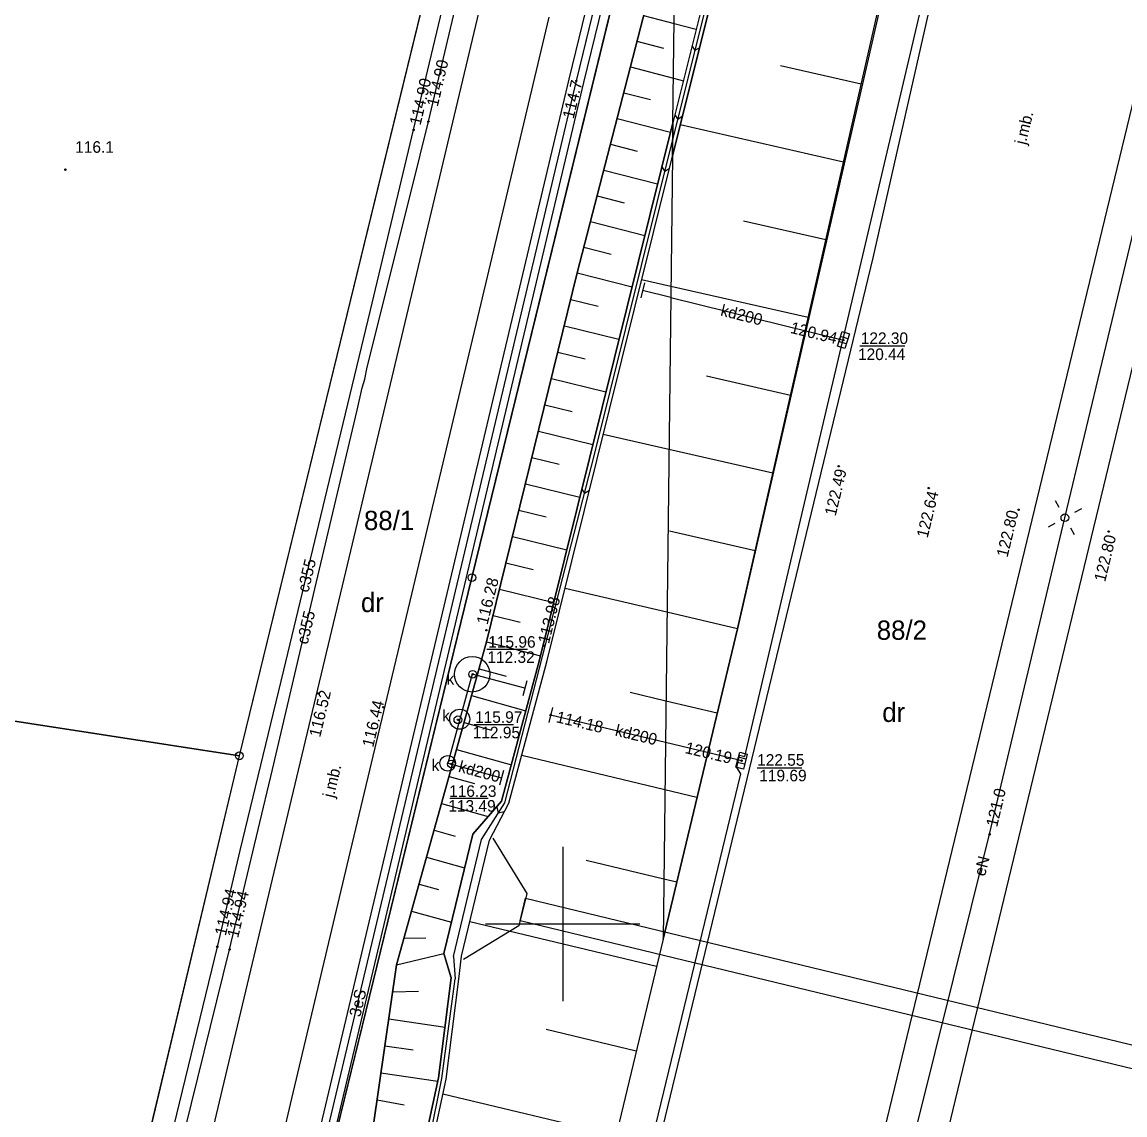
# Model space of a CAD drawing. Extents: x 6424617 to 6425697, y 5665845 to 5667190.
# Drawn here: x 6425265 to 6425336.4, y 5666387.6 to 5666458.4 of the extents above; entities that cross this region are included whole.
import ezdxf

# ---------------------------------------------------------------- set-up
doc = ezdxf.new("R2010")
doc.units = 0
for name, color, linetype in [('Warstwa 1', 7, 'Continuous'), ('Warstwa 10', 7, 'Continuous'), ('Warstwa 11', 7, 'Continuous'), ('Warstwa 12', 7, 'Continuous'), ('Warstwa 13', 7, 'Continuous'), ('Warstwa 14', 7, 'Continuous'), ('Warstwa 15', 7, 'Continuous'), ('Warstwa 16', 7, 'Continuous'), ('Warstwa 2', 7, 'Continuous'), ('Warstwa 20', 7, 'Continuous'), ('Warstwa 21', 7, 'Continuous'), ('Warstwa 22', 7, 'Continuous'), ('Warstwa 25', 7, 'Continuous'), ('Warstwa 4', 7, 'Continuous'), ('Warstwa 47', 7, 'Continuous'), ('Warstwa 5', 7, 'Continuous'), ('Warstwa 6', 7, 'Continuous'), ('Warstwa 61', 7, 'Continuous'), ('Warstwa 63', 7, 'Continuous'), ('Warstwa 8', 7, 'Continuous'), ('Warstwa 9', 7, 'Continuous')]:
    doc.layers.add(name, color=color, linetype=linetype)

msp = doc.modelspace()

# ---------------------------------------------------------------- linework, layer by layer
at = {"layer": 'Warstwa 1'}
for p, q in [((6425294.11, 5666422.45), (6425333.09, 5666581.65)), ((6425294.11, 5666422.45), (6425333.09, 5666581.65)), ((6425279.037, 5666410.906), (6425312.219, 5666546.795)), ((6425279.037, 5666410.906), (6425312.219, 5666546.795)), ((6425272.8, 5666335.34), (6425294.11, 5666422.45)), ((6425272.8, 5666335.34), (6425294.11, 5666422.45)), ((6425251.855, 5666415.084), (6425279.037, 5666410.906)), ((6425251.855, 5666415.084), (6425279.037, 5666410.906)), ((6425244.275, 5666264.977), (6425279.037, 5666410.906)), ((6425244.275, 5666264.977), (6425279.037, 5666410.906))]:
    msp.add_line(p, q, dxfattribs=at)
at = {"layer": 'Warstwa 10'}
for points in [[(6425267.728, 5666315.146), (6425271.19, 5666329.86), (6425276.57, 5666352.13), (6425283.28, 5666380.44), (6425290.28, 5666409.92), (6425300.88, 5666454.64), (6425307.494, 5666481.767)], [(6425295.47, 5666405.57), (6425297.66, 5666401.99), (6425297.15, 5666399.9), (6425293.57, 5666397.71)]]:
    msp.add_lwpolyline(points, dxfattribs=at)
for centre in [(6425294.11, 5666422.45), (6425279.037, 5666410.906)]:
    msp.add_circle(centre, 0.25, dxfattribs=at)
at = {"layer": 'Warstwa 12'}
for points in [[(6425274.8, 5666386.88), (6425277.61, 5666398.54), (6425279.1, 5666404.78), (6425281.92, 5666416.45), (6425284.73, 5666428.13), (6425287.53, 5666439.79), (6425290.33, 5666451.46), (6425293.1, 5666463.15), (6425295.91, 5666474.81), (6425298.69, 5666486.5), (6425301.54, 5666498.35), (6425304.4, 5666509.95), (6425307.24, 5666521.52), (6425307.5, 5666522.71), (6425307.25, 5666523.17), (6425306.05, 5666523.49), (6425298.26, 5666525.66), (6425296.82, 5666526.06), (6425295.28, 5666526.18), (6425283.35, 5666527.26), (6425271.38, 5666528.38), (6425259.45, 5666529.58)], [(6425305.48, 5666314.773), (6425311.14, 5666338.26), (6425315.72, 5666356.59), (6425314.85, 5666358.59), (6425315.59, 5666360.88), (6425316.68, 5666361.57), (6425321.81, 5666382.32), (6425327.66, 5666405.82), (6425332.54, 5666426.33), (6425338.92, 5666452.89), (6425344.68, 5666476.52), (6425348.06, 5666490.52), (6425353.32, 5666512.48), (6425356.9, 5666527.18)], [(6425275.52, 5666386.72), (6425278.4, 5666398.36), (6425281.19, 5666410.02), (6425283.93, 5666421.72), (6425286.67, 5666433.31), (6425286.99, 5666434.74), (6425287.17, 5666435.32), (6425287.32, 5666436.08), (6425290.21, 5666447.65), (6425291.29, 5666452), (6425294.06, 5666463.71), (6425296.87, 5666475.37), (6425299.68, 5666487.06), (6425302.52, 5666498.64), (6425305.3, 5666510.33), (6425307.971, 5666521.283)], [(6425306.998, 5666440.608), (6425305.17, 5666441.06)], [(6425306.998, 5666440.608), (6425317.94, 5666437.9), (6425318.19, 5666437.84)], [(6425297.54, 5666415.28), (6425294.13, 5666416.19), (6425293.32, 5666413.28), (6425292.54, 5666410.42), (6425296.02, 5666409.48)], [(6425306.65, 5666411.771), (6425299.21, 5666413.55)], [(6425311.59, 5666410.59), (6425311.34, 5666410.65), (6425306.65, 5666411.771)]]:
    msp.add_lwpolyline(points, dxfattribs=at)
at = {"layer": 'Warstwa 13'}
msp.add_circle((6425267.765, 5666448.883), 0.045, dxfattribs=at)
at = {"layer": 'Warstwa 14'}
for p, q in [((6425322.159, 5666437.447), (6425319.248, 5666437.447)), ((6425297.719, 5666417.786), (6425295.086, 5666417.786)), ((6425296.794, 5666412.918), (6425294.261, 5666412.918)), ((6425315.482, 5666410.1), (6425312.588, 5666410.1)), ((6425295.156, 5666408.136), (6425292.688, 5666408.136))]:
    msp.add_line(p, q, dxfattribs=at)
for centre in [(6425300.88, 5666454.64), (6425291.29, 5666452), (6425290.33, 5666451.46), (6425317.94, 5666437.9), (6425318.19, 5666437.84), (6425294.16, 5666416.19), (6425293.2, 5666413.24), (6425299.21, 5666413.55), (6425292.77, 5666410.38), (6425311.34, 5666410.65), (6425311.59, 5666410.59), (6425327.66, 5666405.82), (6425277.61, 5666398.54), (6425278.4, 5666398.36)]:
    msp.add_circle(centre, 0.045, dxfattribs=at)
at = {"layer": 'Warstwa 16'}
for centre, radius in [((6425294.13, 5666416.19), 1.15), ((6425293.32, 5666413.28), 0.65), ((6425292.54, 5666410.42), 0.5)]:
    msp.add_circle(centre, radius, dxfattribs=at)
at = {"layer": 'Warstwa 2'}
msp.add_circle((6425332.54, 5666426.33), 0.25, dxfattribs=at)
at = {"layer": 'Warstwa 20'}
for points in [[(6425306.496, 5666399.029), (6425311.317, 5666419.144), (6425338.808, 5666540.067), (6425344.652, 5666564.235)], [(6425292.98, 5666380.282), (6425290.492, 5666380.934), (6425289.337, 5666381.236), (6425286.21, 5666382.055), (6425287.707, 5666386.869), (6425289.227, 5666397.355), (6425295.057, 5666418.297), (6425300.94, 5666442.189), (6425307.315, 5666466.947)], [(6425306.496, 5666399.029), (6425300.821, 5666375.348), (6425289.41, 5666327.719), (6425285.185, 5666318.653), (6425284.331, 5666314.945)]]:
    msp.add_lwpolyline(points, dxfattribs=at)
at = {"layer": 'Warstwa 21'}
for p, q in [((6425305.29, 5666441.545), (6425305.05, 5666440.575)), ((6425297.67, 5666415.763), (6425297.41, 5666414.797)), ((6425299.327, 5666414.036), (6425299.093, 5666413.064)), ((6425296.15, 5666409.963), (6425295.89, 5666408.997))]:
    msp.add_line(p, q, dxfattribs=at)
for points in [[(6425307.108, 5666449.766), (6425311.778, 5666468.481), (6425334.917, 5666564.352)], [(6425334.457, 5666564.358), (6425324.684, 5666524.027), (6425311.3, 5666468.61), (6425307.134, 5666451.915)], [(6425292.98, 5666380.282), (6425290.684, 5666381.655), (6425289.535, 5666381.982), (6425291.018, 5666385.749), (6425291.946, 5666390.044), (6425292.773, 5666396.511), (6425292.291, 5666398.09), (6425294.162, 5666405.839), (6425296.03, 5666407.966), (6425298.497, 5666417.135), (6425304.161, 5666440), (6425307.134, 5666451.915)], [(6425270.982, 5666315.107), (6425272.032, 5666319.27), (6425277.811, 5666333.541), (6425285.262, 5666361.705), (6425288.33, 5666373.734), (6425289.376, 5666376.843), (6425292.365, 5666377.252), (6425292.98, 5666380.282), (6425290.684, 5666381.655), (6425291.516, 5666385.64), (6425292.444, 5666389.955), (6425293.272, 5666396.442), (6425293.428, 5666397.92), (6425295.255, 5666405.439), (6425296.508, 5666407.837), (6425298.975, 5666417.006), (6425304.639, 5666439.871), (6425307.108, 5666449.766)]]:
    msp.add_lwpolyline(points, dxfattribs=at)
at = {"layer": 'Warstwa 22'}
msp.add_lwpolyline([(6425352.7, 5666388.73), (6425359.81, 5666387.02), (6425359.721, 5666386.659), (6425384.611, 5666380.644), (6425384.259, 5666379.186), (6425359.369, 5666385.201), (6425359.28, 5666384.84), (6425352.17, 5666386.56), (6425352.257, 5666386.916), (6425297.227, 5666400.216), (6425297.583, 5666401.674), (6425352.613, 5666388.374), (6425352.7, 5666388.73)], dxfattribs=at)
at = {"layer": 'Warstwa 25'}
for centre in [(6425317.879, 5666429.669), (6425323.715, 5666428.253), (6425329.542, 5666426.847), (6425335.378, 5666425.431), (6425295.054, 5666419.04), (6425298.779, 5666418.04), (6425284.113, 5666414.953), (6425288.368, 5666414.056)]:
    msp.add_circle(centre, 0.045, dxfattribs=at)
at = {"layer": 'Warstwa 4'}
for p, q in [((6425318.373, 5666437.596), (6425317.898, 5666437.752)), ((6425318.482, 5666437.928), (6425318.007, 5666438.084)), ((6425311.789, 5666410.359), (6425311.305, 5666410.482)), ((6425311.875, 5666410.698), (6425311.391, 5666410.821))]:
    msp.add_line(p, q, dxfattribs=at)
for points in [[(6425318.583, 5666438.237), (6425318.272, 5666437.287), (6425317.797, 5666437.443), (6425318.108, 5666438.393)], [(6425311.956, 5666411.013), (6425311.709, 5666410.044), (6425311.224, 5666410.167), (6425311.471, 5666411.136)]]:
    msp.add_lwpolyline(points, close=True, dxfattribs=at)
for points in [[(6425332.174, 5666426.985), (6425331.93, 5666427.421)], [(6425333.195, 5666426.696), (6425333.631, 5666426.94)], [(6425331.885, 5666425.964), (6425331.449, 5666425.72)], [(6425332.906, 5666425.675), (6425333.15, 5666425.239)]]:
    msp.add_lwpolyline(points, dxfattribs=at)
for centre in [(6425294.16, 5666416.19), (6425293.2, 5666413.24), (6425292.77, 5666410.38)]:
    msp.add_circle(centre, 0.25, dxfattribs=at)
at = {"layer": 'Warstwa 47'}
for points in [[(6425344.651, 5666564.235), (6425344.106, 5666562.008), (6425311.317, 5666419.144), (6425306.496, 5666399.029)], [(6425306.496, 5666399.029), (6425300.821, 5666375.348), (6425289.41, 5666327.719), (6425285.185, 5666318.653), (6425284.331, 5666314.945)]]:
    msp.add_lwpolyline(points, dxfattribs=at)
at = {"layer": 'Warstwa 6'}
for points in [[(6425244.275, 5666264.977), (6425279.037, 5666410.906), (6425312.219, 5666546.795), (6425313.029, 5666550.146), (6425358.794, 5666739.45), (6425345.837, 5666783.728), (6425348.185, 5666793.45), (6425355.292, 5666837.846), (6425351.457, 5666842.463), (6425355.995, 5666841.398), (6425356.96, 5666840.82), (6425392.62, 5666819.33), (6425392.36, 5666816.84), (6425379.44, 5666763.67), (6425335.03, 5666581.17), (6425333.09, 5666581.65), (6425294.11, 5666422.45), (6425272.8, 5666335.34)], [(6425392.36, 5666816.84), (6425379.44, 5666763.67), (6425335.03, 5666581.17), (6425333.09, 5666581.65), (6425294.11, 5666422.45), (6425272.8, 5666335.34)], [(6425306.368, 5666388.415), (6425311.528, 5666409.747), (6425311.275, 5666410.152), (6425311.459, 5666410.938), (6425311.798, 5666410.862), (6425324.365, 5666464.253), (6425324.113, 5666464.668), (6425324.297, 5666465.454), (6425324.626, 5666465.379), (6425330.531, 5666491.58), (6425330.278, 5666491.995), (6425330.472, 5666492.782), (6425330.801, 5666492.706), (6425336.716, 5666518.898), (6425336.453, 5666519.323), (6425336.638, 5666520.11), (6425336.966, 5666520.034), (6425342.505, 5666544.261), (6425342.253, 5666544.676), (6425342.437, 5666545.463), (6425342.766, 5666545.387), (6425347.315, 5666564.203)], [(6425288.589, 5666314.894), (6425292.222, 5666329.989), (6425291.989, 5666330.384), (6425292.173, 5666331.171), (6425292.512, 5666331.084), (6425298.36, 5666355.247), (6425298.107, 5666355.651), (6425298.291, 5666356.438), (6425298.62, 5666356.362), (6425304.943, 5666382.487), (6425304.691, 5666382.892), (6425304.875, 5666383.678), (6425304.875, 5666383.678), (6425305.204, 5666383.602), (6425306.368, 5666388.415)]]:
    msp.add_lwpolyline(points, dxfattribs=at)
for points in [[(6425258.718, 5666441.763), (6425251.855, 5666415.084), (6425279.037, 5666410.906), (6425312.219, 5666546.795), (6425309.227, 5666547.531), (6425297.85, 5666522.097), (6425294.373, 5666514.928), (6425272.539, 5666497.33)], [(6425217.631, 5666278.959), (6425217.156, 5666267.745), (6425221.085, 5666266.797), (6425231.986, 5666266.785), (6425236.914, 5666266.626), (6425244.275, 5666264.977), (6425279.037, 5666410.906), (6425251.855, 5666415.084)]]:
    msp.add_lwpolyline(points, close=True, dxfattribs=at)
at = {"layer": 'Warstwa 61'}
msp.add_lwpolyline([(6425267.728, 5666315.146), (6425267.754, 5666315.255), (6425271.19, 5666329.86), (6425276.57, 5666352.13), (6425283.28, 5666380.44), (6425290.28, 5666409.92), (6425300.88, 5666454.64), (6425306.981, 5666479.664), (6425307.494, 5666481.768)], dxfattribs=at)
at = {"layer": 'Warstwa 63'}
for p, q in [((6425300, 5666405), (6425300, 5666395)), ((6425305, 5666400), (6425295, 5666400))]:
    msp.add_line(p, q, dxfattribs=at)
at = {"layer": 'Warstwa 8'}
for p, q in [((6425320.124, 5666443.173), (6425342.162, 5666540.747)), ((6425306.044, 5666325.418), (6425357.544, 5666538.388)), ((6425309.895, 5666324.328), (6425361.428, 5666537.448)), ((6425290.103, 5666440.344), (6425295.201, 5666461.749)), ((6425294.486, 5666439.304), (6425299.118, 5666458.757)), ((6425306.342, 5666386.207), (6425320.124, 5666443.173)), ((6425285.936, 5666422.833), (6425290.103, 5666440.344)), ((6425290.773, 5666423.736), (6425294.486, 5666439.304)), ((6425286.141, 5666404.273), (6425290.773, 5666423.736)), ((6425281.303, 5666403.37), (6425285.936, 5666422.833)), ((6425282.439, 5666388.705), (6425286.141, 5666404.273)), ((6425278.056, 5666389.755), (6425281.303, 5666403.37)), ((6425273.889, 5666372.234), (6425278.056, 5666389.755)), ((6425277.806, 5666369.252), (6425282.439, 5666388.705))]:
    msp.add_line(p, q, dxfattribs=at)
for points in [[(6425307.521, 5666483.989), (6425300.394, 5666454.757), (6425289.794, 5666410.035), (6425282.794, 5666380.555), (6425276.084, 5666352.246), (6425270.704, 5666329.976), (6425267.215, 5666315.152)], [(6425268.241, 5666315.14), (6425271.676, 5666329.744), (6425277.056, 5666352.014), (6425283.766, 5666380.325), (6425290.766, 5666409.805), (6425301.366, 5666454.523), (6425307.467, 5666479.546)]]:
    msp.add_lwpolyline(points, dxfattribs=at)
at = {"layer": 'Warstwa 9'}
for p, q in [((6425307.121, 5666450.84), (6425309.396, 5666459.917)), ((6425305.236, 5666458.873), (6425307.212, 5666458.364)), ((6425307.212, 5666458.364), (6425308.651, 5666457.994)), ((6425304.806, 5666457.204), (6425306.52, 5666456.763)), ((6425308.382, 5666456.915), (6425308.566, 5666456.607)), ((6425308.859, 5666456.782), (6425308.566, 5666456.607)), ((6425304.377, 5666455.536), (6425307.169, 5666454.817)), ((6425319.336, 5666454.414), (6425314.099, 5666455.604)), ((6425307.169, 5666454.817), (6425307.817, 5666454.65)), ((6425303.948, 5666453.868), (6425305.674, 5666453.423)), ((6425303.518, 5666452.199), (6425306.983, 5666451.307)), ((6425307.267, 5666452.447), (6425307.448, 5666452.144)), ((6425307.746, 5666452.323), (6425307.448, 5666452.144)), ((6425318.19, 5666449.375), (6425307.611, 5666451.78)), ((6425302.047, 5666430.422), (6425307.121, 5666450.841)), ((6425303.088, 5666450.53), (6425304.827, 5666450.083)), ((6425306.421, 5666449.057), (6425306.603, 5666448.755)), ((6425306.9, 5666448.934), (6425306.603, 5666448.755)), ((6425302.658, 5666448.862), (6425306.148, 5666447.964)), ((6425302.228, 5666447.194), (6425303.98, 5666446.743)), ((6425301.799, 5666445.526), (6425305.314, 5666444.621)), ((6425317.044, 5666444.336), (6425311.702, 5666445.551)), ((6425301.37, 5666443.858), (6425303.135, 5666443.408)), ((6425300.94, 5666442.189), (6425304.485, 5666441.297)), ((6425307.006, 5666441.319), (6425305.108, 5666441.751)), ((6425315.899, 5666439.298), (6425307.006, 5666441.319)), ((6425300.52, 5666440.482), (6425302.292, 5666440.042)), ((6425300.1, 5666438.776), (6425303.642, 5666437.905)), ((6425299.68, 5666437.07), (6425301.45, 5666436.634)), ((6425299.259, 5666435.363), (6425302.797, 5666434.493)), ((6425314.754, 5666434.26), (6425309.309, 5666435.497)), ((6425298.839, 5666433.657), (6425300.607, 5666433.222)), ((6425298.419, 5666431.95), (6425301.952, 5666431.081)), ((6425306.879, 5666430.751), (6425302.62, 5666431.719)), ((6425296.246, 5666407.87), (6425302.047, 5666430.422)), ((6425313.608, 5666429.221), (6425306.879, 5666430.751)), ((6425297.998, 5666430.243), (6425299.764, 5666429.809)), ((6425297.578, 5666428.536), (6425301.106, 5666427.668)), ((6425301.234, 5666428.183), (6425301.399, 5666427.903)), ((6425301.721, 5666428.093), (6425301.399, 5666427.903)), ((6425297.158, 5666426.83), (6425298.921, 5666426.396)), ((6425312.462, 5666424.182), (6425306.924, 5666425.458)), ((6425296.738, 5666425.123), (6425300.261, 5666424.256)), ((6425296.318, 5666423.416), (6425298.078, 5666422.983)), ((6425306.752, 5666420.208), (6425300.149, 5666421.747)), ((6425295.897, 5666421.71), (6425299.416, 5666420.844)), ((6425295.477, 5666420.004), (6425297.232, 5666419.557)), ((6425311.317, 5666419.144), (6425306.752, 5666420.208)), ((6425295.057, 5666418.297), (6425298.557, 5666417.378)), ((6425294.571, 5666416.552), (6425296.326, 5666416.077)), ((6425294.085, 5666414.807), (6425297.607, 5666413.827)), ((6425306.682, 5666414.455), (6425304.374, 5666415.001)), ((6425310.005, 5666413.67), (6425306.682, 5666414.455)), ((6425293.6, 5666413.062), (6425295.368, 5666412.569)), ((6425293.114, 5666411.316), (6425296.666, 5666410.328)), ((6425306.613, 5666408.694), (6425297.337, 5666410.917)), ((6425292.628, 5666409.571), (6425294.272, 5666409.114)), ((6425308.693, 5666408.195), (6425306.613, 5666408.694)), ((6425292.142, 5666407.826), (6425295.168, 5666406.984)), ((6425294.724, 5666405.492), (6425296.246, 5666407.87)), ((6425295.718, 5666407.611), (6425295.811, 5666407.191)), ((6425296.217, 5666407.28), (6425295.811, 5666407.191)), ((6425291.656, 5666406.081), (6425293.028, 5666405.699)), ((6425292.91, 5666397.908), (6425294.724, 5666405.492)), ((6425291.17, 5666404.336), (6425293.634, 5666403.651)), ((6425306.543, 5666402.921), (6425301.517, 5666404.126)), ((6425290.684, 5666402.59), (6425291.946, 5666402.24)), ((6425307.381, 5666402.72), (6425306.543, 5666402.921)), ((6425290.199, 5666400.845), (6425292.783, 5666400.126)), ((6425306.069, 5666397.246), (6425293.969, 5666400.147)), ((6425289.713, 5666399.1), (6425291.125, 5666399.104)), ((6425289.227, 5666397.355), (6425292.291, 5666398.09)), ((6425292.91, 5666397.908), (6425293.034, 5666396.456)), ((6425292.161, 5666389.994), (6425293.034, 5666396.456)), ((6425288.974, 5666395.608), (6425290.651, 5666395.659)), ((6425288.72, 5666393.86), (6425292.366, 5666393.332)), ((6425304.757, 5666391.772), (6425298.93, 5666393.169)), ((6425288.467, 5666392.112), (6425290.3, 5666391.846)), ((6425288.214, 5666390.364), (6425291.9, 5666389.83)), ((6425291.186, 5666385.187), (6425292.161, 5666389.994)), ((6425303.445, 5666386.297), (6425292.235, 5666388.984)), ((6425287.96, 5666388.616), (6425289.729, 5666388.291))]:
    msp.add_line(p, q, dxfattribs=at)
for points in [[(6425306.496, 5666399.029), (6425311.317, 5666419.144), (6425338.808, 5666540.067), (6425344.652, 5666564.235), (6425334.917, 5666564.352), (6425311.778, 5666468.481), (6425307.108, 5666449.766)], [(6425307.108, 5666449.766), (6425311.778, 5666468.481), (6425334.917, 5666564.352), (6425334.457, 5666564.358), (6425324.684, 5666524.027), (6425311.3, 5666468.61), (6425307.134, 5666451.915)], [(6425334.457, 5666564.358), (6425324.684, 5666524.027), (6425311.3, 5666468.61), (6425307.134, 5666451.915), (6425307.315, 5666466.947), (6425307.814, 5666468.883), (6425314.453, 5666496.422), (6425321.245, 5666524.099), (6425327.788, 5666549.679), (6425331.487, 5666564.394)], [(6425286.21, 5666382.055), (6425289.337, 5666381.236), (6425290.492, 5666380.934), (6425292.98, 5666380.282), (6425290.684, 5666381.655), (6425289.535, 5666381.982), (6425291.018, 5666385.749), (6425291.946, 5666390.044), (6425292.773, 5666396.511), (6425292.291, 5666398.09), (6425294.162, 5666405.839), (6425296.03, 5666407.966), (6425298.497, 5666417.135), (6425304.161, 5666440), (6425307.134, 5666451.915), (6425307.315, 5666466.947), (6425300.94, 5666442.189), (6425295.057, 5666418.297), (6425289.227, 5666397.355), (6425287.707, 5666386.869)], [(6425307.134, 5666451.915), (6425304.161, 5666440), (6425298.497, 5666417.135), (6425296.03, 5666407.966), (6425294.162, 5666405.839), (6425292.291, 5666398.09), (6425292.773, 5666396.511), (6425291.946, 5666390.044), (6425291.018, 5666385.749), (6425289.535, 5666381.982), (6425290.684, 5666381.655), (6425291.516, 5666385.64), (6425292.444, 5666389.955), (6425293.272, 5666396.442), (6425293.428, 5666397.92), (6425295.255, 5666405.439), (6425296.508, 5666407.837), (6425298.975, 5666417.006), (6425304.639, 5666439.871), (6425307.108, 5666449.766)], [(6425306.496, 5666399.029), (6425300.821, 5666375.348), (6425289.41, 5666327.719), (6425285.185, 5666318.653), (6425284.331, 5666314.945), (6425270.982, 5666315.107), (6425272.032, 5666319.27), (6425277.811, 5666333.541), (6425285.262, 5666361.705), (6425288.33, 5666373.734), (6425289.376, 5666376.843), (6425292.365, 5666377.252), (6425292.98, 5666380.282), (6425290.684, 5666381.655), (6425291.516, 5666385.64), (6425292.444, 5666389.955), (6425293.272, 5666396.442), (6425293.428, 5666397.92), (6425295.255, 5666405.439), (6425296.508, 5666407.837), (6425298.975, 5666417.006), (6425304.639, 5666439.871), (6425307.108, 5666449.766)]]:
    msp.add_lwpolyline(points, close=True, dxfattribs=at)

# ---------------------------------------------------------------- texts
at = {"layer": 'Warstwa 11'}
msp.add_text('3eS', height=0.75, rotation=76.64456, dxfattribs=at).set_placement((6425286.871, 5666393.942))
at = {"layer": 'Warstwa 13'}
msp.add_text('116.1', height=0.75, dxfattribs=at).set_placement((6425268.395, 5666449.977))
for s, rotation, p in [('kd200', 346.10089, (6425310.175, 5666439.436)), ('c355', 76.47268, (6425283.509, 5666421.45)), ('c355', 76.82218, (6425283.464, 5666418.085)), ('kd200', 346.55352, (6425303.346, 5666412.22)), ('kd200', 344.88622, (6425293.188, 5666409.883)), ('eN', 76.02004, (6425327.358, 5666403.055))]:
    msp.add_text(s, height=0.75, rotation=rotation, dxfattribs=at).set_placement(p)
at = {"layer": 'Warstwa 14'}
for s, rotation, p in [('114.90', 76.6904, (6425291.893, 5666452.921)), ('114.90', 76.66748, (6425290.777, 5666451.719)), ('114.7', 76.66748, (6425300.7, 5666452.139)), ('120.94', 346.10089, (6425314.697, 5666438.316)), ('114.18', 346.55352, (6425299.522, 5666413.089)), ('120.19', 346.55925, (6425307.877, 5666411.092)), ('121.0', 76.61592, (6425328.147, 5666406.253)), ('114.94', 76.57008, (6425278.155, 5666399.208)), ('114.94', 76.54143, (6425278.955, 5666399.066))]:
    msp.add_text(s, height=0.75, rotation=rotation, dxfattribs=at).set_placement(p)
for s, p in [('120.44', (6425319.132, 5666436.548)), ('112.32', (6425295.111, 5666416.926)), ('112.95', (6425294.161, 5666412.042)), ('119.69', (6425312.734, 5666409.253)), ('113.49', (6425292.581, 5666407.287))]:
    msp.add_text(s, height=0.75, dxfattribs=at).set_placement(p)
at = {"layer": 'Warstwa 15'}
for s, height, p in [('122.30', 0.75, (6425319.31, 5666437.589)), ('88/1', 1.25, (6425287.114, 5666425.532)), ('88/2', 1.25, (6425320.348, 5666418.423)), ('115.96', 0.75, (6425295.169, 5666417.911)), ('115.97', 0.75, (6425294.311, 5666413.042)), ('122.55', 0.75, (6425312.593, 5666410.263)), ('116.23', 0.75, (6425292.632, 5666408.243))]:
    msp.add_text(s, height=height, dxfattribs=at).set_placement(p)
at = {"layer": 'Warstwa 2'}
for p in [(6425286.916, 5666420.218), (6425320.703, 5666413.1)]:
    msp.add_text('dr', height=1.25, dxfattribs=at).set_placement(p)
at = {"layer": 'Warstwa 25'}
for s, rotation, p in [('122.49', 76.39819, (6425317.684, 5666426.406)), ('122.64', 76.39819, (6425323.644, 5666424.977)), ('122.80', 76.39819, (6425328.822, 5666423.729)), ('122.80', 76.40392, (6425335.15, 5666422.136)), ('116.28', 76.16901, (6425295.123, 5666419.361)), ('113.98', 76.0888, (6425299.103, 5666418.129)), ('116.52', 76.61019, (6425284.274, 5666412.067)), ('116.44', 76.61592, (6425287.711, 5666411.417))]:
    msp.add_text(s, height=0.75, rotation=rotation, dxfattribs=at).set_placement(p)
at = {"layer": 'Warstwa 5'}
for p in [(6425292.466, 5666415.514), (6425292.181, 5666413.132), (6425291.497, 5666409.922)]:
    msp.add_text('k', height=0.75, dxfattribs=at).set_placement(p)
at = {"layer": 'Warstwa 8'}
for rotation, p in [(76.40392, (6425329.998, 5666450.463)), (76.61592, (6425285.154, 5666408.147))]:
    msp.add_text('j.mb.', height=0.75, rotation=rotation, dxfattribs=at).set_placement(p)

doc.saveas('drawing.dxf')
